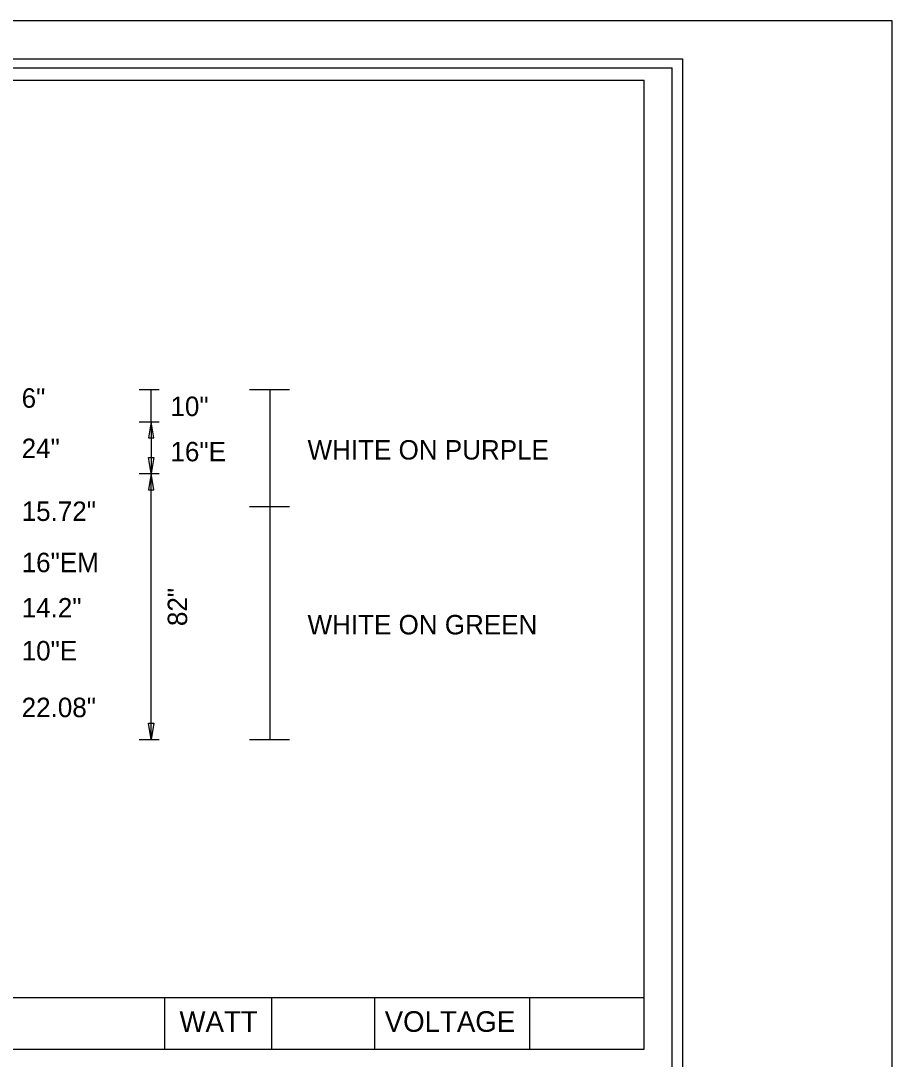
# Model space of a CAD drawing. Extents: x 122633 to 124574, y -23288 to -22025.
# Drawn here: x 124305.3 to 124574.1, y -22345.1 to -22024.7 of the extents above; entities that cross this region are included whole.
import ezdxf

# ---------------------------------------------------------------- set-up
doc = ezdxf.new("R2010")
doc.units = 0
for name, color, linetype in [('GSDims', 7, 'Continuous'), ('PlotBorder_dp', 7, 'Continuous'), ('SheetBorder_dp', 7, 'Continuous'), ('SheetLinesMisc2_dp', 7, 'Continuous'), ('TextMinor', 7, 'Continuous')]:
    doc.layers.add(name, color=color, linetype=linetype)

msp = doc.modelspace()

# ---------------------------------------------------------------- linework, layer by layer
at = {"layer": 'GSDims'}
for p, q in [((124341.76, -22138.41), (124348.01, -22138.41)), ((124345.51, -22148.41), (124345.51, -22138.41)), ((124375.83, -22138.41), (124388.16, -22138.41)), ((124382.08, -22138.41), (124382.08, -22174.61)), ((124341.76, -22148.41), (124348.01, -22148.41)), ((124341.76, -22148.41), (124348.01, -22148.41)), ((124345.51, -22148.41), (124345.51, -22164.41)), ((124341.76, -22164.41), (124348.01, -22164.41)), ((124341.76, -22164.41), (124348.01, -22164.41)), ((124345.51, -22246.41), (124345.51, -22164.41)), ((124375.83, -22174.61), (124388.16, -22174.61)), ((124382.08, -22174.61), (124382.08, -22246.41)), ((124341.76, -22246.41), (124348.01, -22246.41)), ((124375.83, -22246.41), (124388.16, -22246.41))]:
    msp.add_line(p, q, dxfattribs=at)
for points in [[(124345.51, -22148.41), (124344.68, -22153.41), (124346.34, -22153.41)], [(124345.51, -22164.41), (124344.68, -22159.41), (124346.34, -22159.41)], [(124345.51, -22164.41), (124344.68, -22169.41), (124346.34, -22169.41)], [(124345.51, -22246.41), (124344.68, -22241.41), (124346.34, -22241.41)]]:
    msp.add_lwpolyline(points, close=True, dxfattribs=at)
at = {"layer": 'PlotBorder_dp'}
msp.add_lwpolyline([(122633.11, -23271.62), (124574.11, -23271.62), (124574.11, -22024.68), (122633.11, -22024.68)], close=True, dxfattribs=at)
at = {"layer": 'SheetBorder_dp'}
for p, q in [((122697.81, -22036.45), (124509.41, -22036.45)), ((124509.41, -22036.45), (124509.41, -23259.86))]:
    msp.add_line(p, q, dxfattribs=at)
at = {"layer": 'SheetLinesMisc2_dp'}
for p, q in [((122701.01, -22039.22), (124506.26, -22039.22)), ((124506.27, -23162.98), (124506.27, -22039.23)), ((123883.65, -22042.97), (124497.63, -22042.97)), ((124497.63, -22342.04), (124497.63, -22042.97)), ((123883.65, -22326.02), (124497.63, -22326.02)), ((124349.65, -22326.02), (124349.65, -22342.04)), ((124382.59, -22326.02), (124382.59, -22342.04)), ((124414.35, -22326.02), (124414.35, -22342.04)), ((124462.17, -22326.02), (124462.17, -22342.04)), ((123883.65, -22342.04), (124497.63, -22342.04))]:
    msp.add_line(p, q, dxfattribs=at)

# ---------------------------------------------------------------- texts
at = {"layer": 'GSDims'}
for s, p in [('6"', (124305.54, -22144.09)), ('10"', (124351.44, -22146.66)), ('24"', (124305.54, -22159.62)), ('16"E', (124351.44, -22160.62)), ('WHITE ON PURPLE', (124393.74, -22160.08)), ('15.72"', (124305.54, -22179.02)), ('16"EM', (124305.54, -22194.83)), ('14.2"', (124305.54, -22208.81)), ('WHITE ON GREEN', (124393.74, -22214.03)), ('10"E', (124305.54, -22222.06)), ('22.08"', (124305.54, -22239.56))]:
    msp.add_text(s, height=6, dxfattribs=at).set_placement(p)
msp.add_text('82"', height=6, rotation=90, dxfattribs=at).set_placement((124356.59, -22211.46))
at = {"layer": 'TextMinor'}
for s, p in [('WATT', (124354.22, -22336.67)), ('VOLTAGE', (124417.53, -22336.67))]:
    msp.add_text(s, height=6.377, dxfattribs=at).set_placement(p)

doc.saveas('drawing.dxf')
